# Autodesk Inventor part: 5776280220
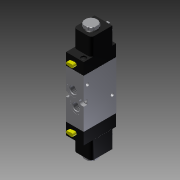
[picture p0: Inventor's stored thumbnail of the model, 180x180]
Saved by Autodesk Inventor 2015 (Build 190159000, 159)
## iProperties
Created: 2013-02
Part Number: 5776280220
Material: Generic
Document SubType Name: Modeling
Designer: Marci
Density: 1 g/cm^3
Appearance: Default
Translation Standard: STEP AP214IS
FileName: 5776280220
PreProcessor: PRO/ENGINEER BY PARAMETRIC TECHNOLOGY CORPORATION, 2006020
PostProcessor: Build: 160, Release: 2012 RTM - Date: Tue 03/01/2011
Sent Units: millimeter
Uncertainty: 0.001
Author: Marci
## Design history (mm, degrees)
node "57762802201"
thread "Thread1" dims "d0" = 10, "d1" = 0
thread "Thread2" dims "d2" = 10, "d3" = 0
thread "Thread3" dims "d4" = 10, "d5" = 0
thread "Thread4" dims "d6" = 10, "d7" = 0
thread "Thread5" dims "d8" = 10, "d9" = 0
thread "Thread6" dims "d10" = 10, "d11" = 0
thread "Thread7" dims "d12" = 10, "d13" = 0
node "5776280220"
node "Base1"
